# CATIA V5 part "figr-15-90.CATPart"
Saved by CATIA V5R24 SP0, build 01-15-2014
Part number: Part1
Bounding box of the stored display mesh (mm): x -45.183 to 59.676, y -22.214 to 29.903, z -4 to 1
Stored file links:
  D:\KAVITA\CATIA V5-6R2014 Project_ Kavita\CATIA V5-6R2014_partfiles\Partfiles\c15_catia_v5-6r2014_prt\figr-15-90.CATPart
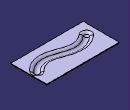
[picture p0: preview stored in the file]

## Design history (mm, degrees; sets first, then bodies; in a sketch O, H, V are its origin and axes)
SheetMetalParameters1: Thickness 1, BendRadius 5, KFactor 0.5 {= log(min(100,max(20*SheetMetalParameters1.BendRadius,SheetMetalParameters1.Thickness)/SheetMetalParameters1.Thickness))/log(100)/2}, ReliefRadialLength 1, ReliefAxialLength 2, MinimumBendRadius 0
Body1 (main body)
  Sketch1 on xy-plane, origin (0, 0, 0), H (1, 0, 0), V (0, 1, 0)
    line L1 (-45.1833, 29.903) -> (59.6761, 29.903)
    line L2 (59.6761, 29.903) -> (59.6761, -22.2137)
    line L3 (59.6761, -22.2137) -> (-45.1833, -22.2137)
    line L4 (-45.1833, -22.2137) -> (-45.1833, 29.903)
    horizontal: L1 H, L3 H
    vertical: L2 V, L4 V
  Wall1: Thickness 1, Profile Sketch1
  Sketch2 on face of Wall1, origin (0, 0, 1), H (1, 0, 0), V (0, 1, 0)
    spline S1 through (-31.3214, -3.7025) (-6.2947, 5.2247) (29.3365, -3.7025) (50.9697, 6.9251)
  d_Stamp1: Stamp_FilletRadius 4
